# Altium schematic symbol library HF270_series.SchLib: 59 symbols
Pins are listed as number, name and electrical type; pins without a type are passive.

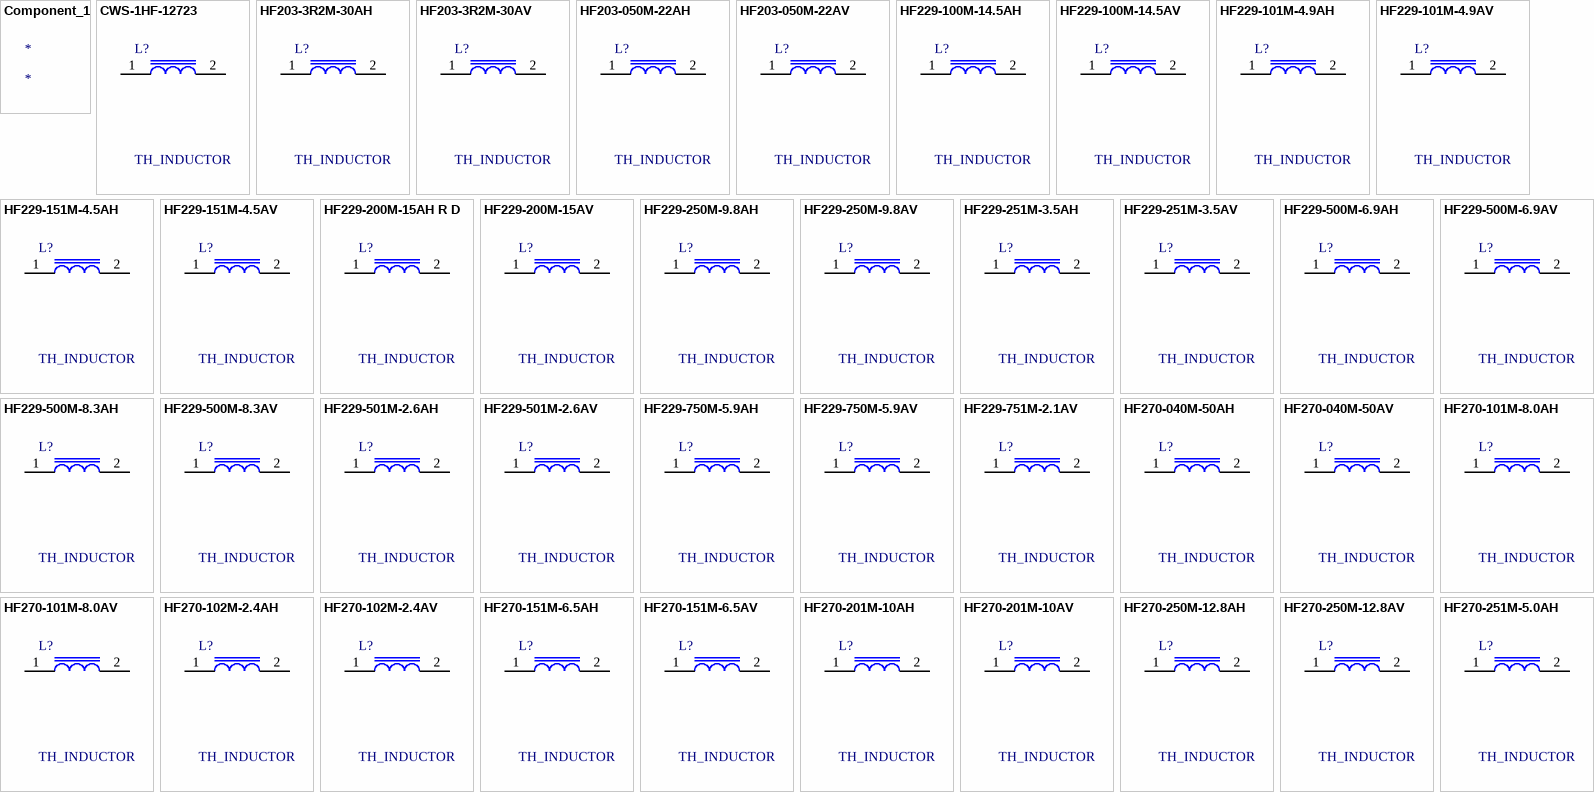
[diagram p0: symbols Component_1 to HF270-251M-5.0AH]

## Component_1
designator *

## CWS-1HF-12723
designator L?, comment TH_INDUCTOR
POWER INDUCTOR 22.0 A, 40 uH, 8 mOhms, OD 34.04 mm, HT 18.03 mm; Manufacturer #1: CWS; Sim.Analog.Prefix: L; Sim.Analog.Order: Model$; Current: 22.0 A; DCR: 8 mOhms; Inductance: 40 uH
footprint CWS-1HF-12723
pins: 1, 2

## HF203-3R2M-30AH
designator L?, comment TH_INDUCTOR
POWER INDUCTOR 30.0 A, 3.20 uH, 1 mOhms, OD 28.45 mm, HT 13.21 mm; Manufacturer #1: CWS; Sim.Analog.Prefix: L; Sim.Analog.Order: Model$; Current: 30.0 A; DCR: 1 mOhms; Inductance: 3.20 uH
footprint HF203-3R2M-30AH
pins: 1, 2

## HF203-3R2M-30AV
designator L?, comment TH_INDUCTOR
POWER INDUCTOR 30.0 A, 3.20 uH, 1 mOhms, OD 27.43 mm, HT 12.7 mm; Manufacturer #1: CWS; Sim.Analog.Prefix: L; Sim.Analog.Order: Model$; Current: 30.0 A; DCR: 1 mOhms; Inductance: 3.20 uH
footprint HF203-3R2M-30AV
pins: 1, 2

## HF203-050M-22AH
designator L?, comment TH_INDUCTOR
POWER INDUCTOR 22.0 A, 5.40 uH, 2 mOhms, OD 27 mm, HT 11.51 mm; Manufacturer #1: CWS; Sim.Analog.Prefix: L; Sim.Analog.Order: Model$; OD: 27 mm; Current: 22.0 A; DCR: 2 mOhms; Inductance: 5.40 uH
footprint HF203-050M-22AH
pins: 1, 2

## HF203-050M-22AV
designator L?, comment TH_INDUCTOR
POWER INDUCTOR 22.0 A, 5.40 uH, 2 mOhms, OD 27 mm, HT 11.51 mm; Manufacturer #1: CWS; Sim.Analog.Prefix: L; Sim.Analog.Order: Model$; OD: 27 mm; Current: 22.0 A; DCR: 2 mOhms; Inductance: 5.40 uH
footprint HF203-050M-22AV
pins: 1, 2

## HF229-100M-14.5AH
designator L?, comment TH_INDUCTOR
POWER INDUCTOR 14.5 A, 10 uH, 8 mOhms, OD 27.94 mm, HT 12.07 mm; Manufacturer #1: CWS; Sim.Analog.Prefix: L; Sim.Analog.Order: Model$; Current: 14.5 A; DCR: 8 mOhms; Inductance: 10 uH
footprint HF229-100M-14.5AH
pins: 1, 2

## HF229-100M-14.5AV
designator L?, comment TH_INDUCTOR
POWER INDUCTOR 14.5 A, 10 uH, 8 mOhms, OD 27.94 mm, HT 12.07 mm; Manufacturer #1: CWS; Sim.Analog.Prefix: L; Sim.Analog.Order: Model$; Current: 14.5 A; DCR: 8 mOhms; Inductance: 10 uH
footprint HF229-100M-14.5AV
pins: 1, 2

## HF229-101M-4.9AH
designator L?, comment TH_INDUCTOR
POWER INDUCTOR 4.9 A, 100 uH, 44 mOhms, OD 27.94 mm, HT 12.07 mm; Manufacturer #1: CWS; Sim.Analog.Prefix: L; Sim.Analog.Order: Model$; Current: 4.9 A; Inductance: 100 uH
footprint HF229-101M-4.9AH
pins: 1, 2

## HF229-101M-4.9AV
designator L?, comment TH_INDUCTOR
POWER INDUCTOR 4.9 A, 100 uH, 44 mOhms, OD 27.94 mm, HT 12.07 mm; Manufacturer #1: CWS; Sim.Analog.Prefix: L; Sim.Analog.Order: Model$; Current: 4.9 A; Inductance: 100 uH
footprint HF229-101M-4.9AV
pins: 1, 2

## HF229-151M-4.5AH
designator L?, comment TH_INDUCTOR
POWER INDUCTOR 4.5 A, 150 uH, 52 mOhms, OD 27.94 mm, HT 12.07 mm; Manufacturer #1: CWS; Sim.Analog.Prefix: L; Sim.Analog.Order: Model$; Current: 4.5 A; Inductance: 150 uH
footprint HF229-151M-4.5AH
pins: 1, 2

## HF229-151M-4.5AV
designator L?, comment TH_INDUCTOR
POWER INDUCTOR 4.5 A, 150 uH, 52 mOhms, OD 27.94 mm, HT 12.07 mm; Manufacturer #1: CWS; Sim.Analog.Prefix: L; Sim.Analog.Order: Model$; Current: 4.5 A; Inductance: 150 uH
footprint HF229-151M-4.5AV
pins: 1, 2

## HF229-200M-15AH R D
designator L?, comment TH_INDUCTOR
POWER INDUCTOR 15.0 A, 20 uH, 8 mOhms, OD 27.94 mm, HT 12.07 mm; Manufacturer #1: CWS; Sim.Analog.Prefix: L; Sim.Analog.Order: Model$; Current: 15.0 A; DCR: 8 mOhms; Inductance: 20 uH
footprint HF229-200M-15AH R D
pins: 1, 2

## HF229-200M-15AV
designator L?, comment TH_INDUCTOR
POWER INDUCTOR 15.0 A, 20 uH, 8 mOhms, OD 27.94 mm, HT 12.07 mm; Manufacturer #1: CWS; Sim.Analog.Prefix: L; Sim.Analog.Order: Model$; Current: 15.0 A; DCR: 8 mOhms; Inductance: 20 uH
footprint HF229-200M-15AV
pins: 1, 2

## HF229-250M-9.8AH
designator L?, comment TH_INDUCTOR
POWER INDUCTOR 9.8 A, 25 uH, 11 mOhms, OD 27.94 mm, HT 12.07 mm; Manufacturer #1: CWS; Sim.Analog.Prefix: L; Sim.Analog.Order: Model$; Current: 9.8 A; Inductance: 25 uH
footprint HF229-250M-9.8AH
pins: 1, 2

## HF229-250M-9.8AV
designator L?, comment TH_INDUCTOR
POWER INDUCTOR 9.8 A, 25 uH, 11 mOhms, OD 27.94 mm, HT 12.07 mm; Manufacturer #1: CWS; Sim.Analog.Prefix: L; Sim.Analog.Order: Model$; Current: 9.8 A; Inductance: 25 uH
footprint HF229-250M-9.8AV
pins: 1, 2

## HF229-251M-3.5AH
designator L?, comment TH_INDUCTOR
POWER INDUCTOR 3.5 A, 250 uH, 88 mOhms, OD 27.94 mm, HT 12.07 mm; Manufacturer #1: CWS; Sim.Analog.Prefix: L; Sim.Analog.Order: Model$; Current: 3.5 A; Inductance: 250 uH
footprint HF229-251M-3.5AH
pins: 1, 2

## HF229-251M-3.5AV
designator L?, comment TH_INDUCTOR
POWER INDUCTOR 3.5 A, 250 uH, 88 mOhms, OD 27.94 mm, HT 12.07 mm; Manufacturer #1: CWS; Sim.Analog.Prefix: L; Sim.Analog.Order: Model$; Current: 3.5 A; Inductance: 250 uH
footprint HF229-251M-3.5AV
pins: 1, 2

## HF229-500M-6.9AH
designator L?, comment TH_INDUCTOR
POWER INDUCTOR 6.9 A, 50 uH, 22 mOhms, OD 27.94 mm, HT 12.07 mm; Manufacturer #1: CWS; Sim.Analog.Prefix: L; Sim.Analog.Order: Model$; Current: 6.9 A; Inductance: 50 uH
footprint HF229-500M-6.9AH
pins: 1, 2

## HF229-500M-6.9AV
designator L?, comment TH_INDUCTOR
POWER INDUCTOR 6.9 A, 50 uH, 22 mOhms, OD 27.94 mm, HT 12.07 mm; Manufacturer #1: CWS; Sim.Analog.Prefix: L; Sim.Analog.Order: Model$; Current: 6.9 A; Inductance: 50 uH
footprint HF229-500M-6.9AV
pins: 1, 2

## HF229-500M-8.3AH
designator L?, comment TH_INDUCTOR
POWER INDUCTOR 8.3 A, 50 uH, 22 mOhms, OD 27.94 mm, HT 12.07 mm; Manufacturer #1: CWS; Sim.Analog.Prefix: L; Sim.Analog.Order: Model$; Current: 8.3 A; Inductance: 50 uH
footprint HF229-500M-8.3AH
pins: 1, 2

## HF229-500M-8.3AV
designator L?, comment TH_INDUCTOR
POWER INDUCTOR 8.3 A, 50 uH, 22 mOhms, OD 27.94 mm, HT 12.07 mm; Manufacturer #1: CWS; Sim.Analog.Prefix: L; Sim.Analog.Order: Model$; Current: 8.3 A; Inductance: 50 uH
footprint HF229-500M-8.3AV
pins: 1, 2

## HF229-501M-2.6AH
designator L?, comment TH_INDUCTOR
POWER INDUCTOR 2.6 A, 500 uH, 160 mOhms, OD 27.94 mm, HT 12.07 mm; Manufacturer #1: CWS; Sim.Analog.Prefix: L; Sim.Analog.Order: Model$; Current: 2.6 A; Inductance: 500 uH
footprint HF229-501M-2.6AH
pins: 1, 2

## HF229-501M-2.6AV
designator L?, comment TH_INDUCTOR
POWER INDUCTOR 2.6 A, 500 uH, 160 mOhms, OD 27.94 mm, HT 12.07 mm; Manufacturer #1: CWS; Sim.Analog.Prefix: L; Sim.Analog.Order: Model$; Current: 2.6 A; Inductance: 500 uH
footprint HF229-501M-2.6AV
pins: 1, 2

## HF229-750M-5.9AH
designator L?, comment TH_INDUCTOR
POWER INDUCTOR 5.9 A, 75 uH, 30 mOhms, OD 27.94 mm, HT 12.07 mm; Manufacturer #1: CWS; Sim.Analog.Prefix: L; Sim.Analog.Order: Model$; Current: 5.9 A; Inductance: 75 uH
footprint HF229-750M-5.9AH
pins: 1, 2

## HF229-750M-5.9AV
designator L?, comment TH_INDUCTOR
POWER INDUCTOR 5.9 A, 75 uH, 30 mOhms, OD 27.94 mm, HT 12.07 mm; Manufacturer #1: CWS; Sim.Analog.Prefix: L; Sim.Analog.Order: Model$; Current: 5.9 A; Inductance: 75 uH
footprint HF229-750M-5.9AV
pins: 1, 2

## HF229-751M-2.1AV
designator L?, comment TH_INDUCTOR
POWER INDUCTOR 2.1 A, 750 uH, 240 mOhms, OD 27.94 mm, HT 12.07 mm; Manufacturer #1: CWS; Sim.Analog.Prefix: L; Sim.Analog.Order: Model$; Current: 2.1 A; Inductance: 750 uH
footprint HF229-751M-2.1AV
pins: 1, 2

## HF270-040M-50AH
designator L?, comment TH_INDUCTOR
POWER INDUCTOR 50.0 A, 4 uH, 1.30 mOhms, OD 36.58 mm, HT 15.49 mm; Manufacturer #1: CWS; Sim.Analog.Prefix: L; Sim.Analog.Order: Model$; Current: 50.0 A; Inductance: 4 uH
footprint HF270-040M-50AH
pins: 1, 2

## HF270-040M-50AV
designator L?, comment TH_INDUCTOR
POWER INDUCTOR 50.0 A, 4 uH, 1.30 mOhms, OD 33.02 mm, HT 43.43 mm; Manufacturer #1: CWS; Sim.Analog.Prefix: L; Sim.Analog.Order: Model$; Current: 50.0 A; Inductance: 4 uH
footprint HF270-040M-50AV
pins: 1, 2

## HF270-101M-8.0AH
designator L?, comment TH_INDUCTOR
POWER INDUCTOR 8.0 A, 100 uH, 23 mOhms, OD 33.02 mm, HT 16.51 mm; Manufacturer #1: CWS; Sim.Analog.Prefix: L; Sim.Analog.Order: Model$; Current: 8.0 A; Inductance: 100 uH
footprint HF270-101M-8.0AH
pins: 1, 2

## HF270-101M-8.0AV
designator L?, comment TH_INDUCTOR
POWER INDUCTOR 8.0 A, 100 uH, 23 mOhms, OD 33.02 mm, HT 16.51 mm; Manufacturer #1: CWS; Sim.Analog.Prefix: L; Sim.Analog.Order: Model$; Current: 8.0 A; Inductance: 100 uH
footprint HF270-101M-8.0AV
pins: 1, 2

## HF270-102M-2.4AH
designator L?, comment TH_INDUCTOR
POWER INDUCTOR 2.4 A, 1000 uH, 235 mOhms, OD 33.02 mm, HT 16.51 mm; Manufacturer #1: CWS; Sim.Analog.Prefix: L; Sim.Analog.Order: Model$; Current: 2.4 A; Inductance: 1000 uH
footprint HF270-102M-2.4AH
pins: 1, 2

## HF270-102M-2.4AV
designator L?, comment TH_INDUCTOR
POWER INDUCTOR 2.4 A, 1000 uH, 235 mOhms, OD 33.02 mm, HT 16.51 mm; Manufacturer #1: CWS; Sim.Analog.Prefix: L; Sim.Analog.Order: Model$; Current: 2.4 A; Inductance: 1000 uH
footprint HF270-102M-2.4AV
pins: 1, 2

## HF270-151M-6.5AH
designator L?, comment TH_INDUCTOR
POWER INDUCTOR 6.5 A, 150 uH, 35 mOhms, OD 33.02 mm, HT 16.51 mm; Manufacturer #1: CWS; Sim.Analog.Prefix: L; Sim.Analog.Order: Model$; Current: 6.5 A; Inductance: 150 uH
footprint HF270-151M-6.5AH
pins: 1, 2

## HF270-151M-6.5AV
designator L?, comment TH_INDUCTOR
POWER INDUCTOR 6.5 A, 150 uH, 35 mOhms, OD 33.02 mm, HT 16.51 mm; Manufacturer #1: CWS; Sim.Analog.Prefix: L; Sim.Analog.Order: Model$; Current: 6.5 A; Inductance: 150 uH
footprint HF270-151M-6.5AV
pins: 1, 2

## HF270-201M-10AH
designator L?, comment TH_INDUCTOR
POWER INDUCTOR 10.0 A, 200 uH, 25 mOhms, OD 33.02 mm, HT 16.51 mm; Manufacturer #1: CWS; Sim.Analog.Prefix: L; Sim.Analog.Order: Model$; Current: 10.0 A; Inductance: 200 uH
footprint HF270-201M-10AH
pins: 1, 2

## HF270-201M-10AV
designator L?, comment TH_INDUCTOR
POWER INDUCTOR 10.0 A, 200 uH, 25 mOhms, OD 33.02 mm, HT 16.51 mm; Manufacturer #1: CWS; Sim.Analog.Prefix: L; Sim.Analog.Order: Model$; Current: 10.0 A; Inductance: 200 uH
footprint HF270-201M-10AV
pins: 1, 2

## HF270-250M-12.8AH
designator L?, comment TH_INDUCTOR
POWER INDUCTOR 12.8 A, 25 uH, 7 mOhms, OD 33.02 mm, HT 16.51 mm; Manufacturer #1: CWS; Sim.Analog.Prefix: L; Sim.Analog.Order: Model$; Current: 12.8 A; DCR: 7 mOhms; Inductance: 25 uH
footprint HF270-250M-12.8AH
pins: 1, 2

## HF270-250M-12.8AV
designator L?, comment TH_INDUCTOR
POWER INDUCTOR 12.8 A, 25 uH, 7 mOhms, OD 33.02 mm, HT 16.51 mm; Manufacturer #1: CWS; Sim.Analog.Prefix: L; Sim.Analog.Order: Model$; Current: 12.8 A; DCR: 7 mOhms; Inductance: 25 uH
footprint HF270-250M-12.8AV
pins: 1, 2

## HF270-251M-5.0AH
designator L?, comment TH_INDUCTOR
POWER INDUCTOR 5.0 A, 250 uH, 60 mOhms, OD 33.02 mm, HT 16.51 mm; Manufacturer #1: CWS; Sim.Analog.Prefix: L; Sim.Analog.Order: Model$; Current: 5.0 A; Inductance: 250 uH
footprint HF270-251M-5.0AH
pins: 1, 2

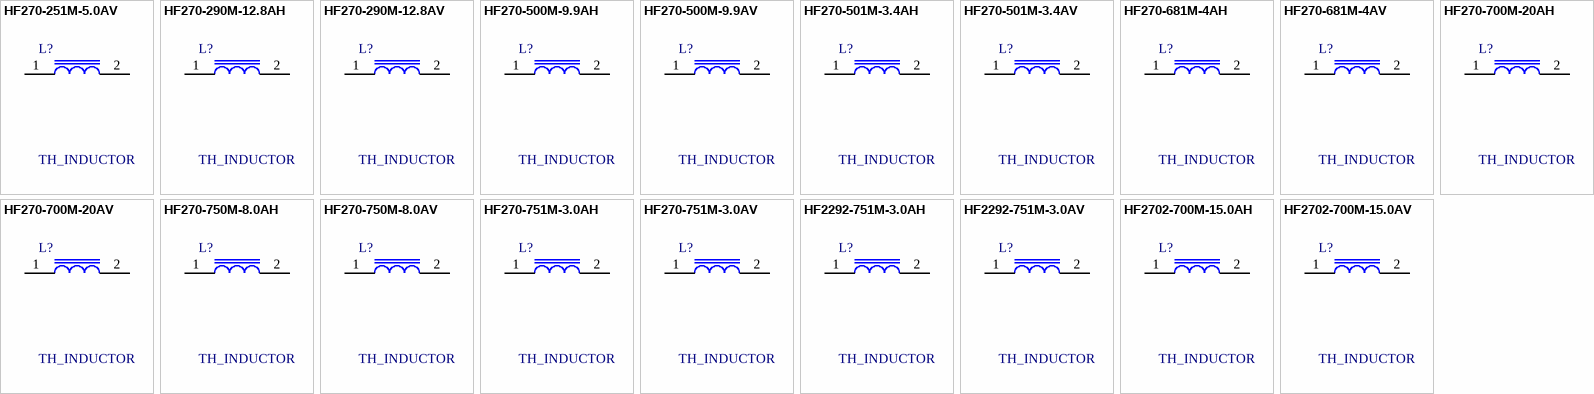
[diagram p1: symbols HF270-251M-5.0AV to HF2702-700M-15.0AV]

## HF270-251M-5.0AV
designator L?, comment TH_INDUCTOR
POWER INDUCTOR 5.0 A, 250 uH, 60 mOhms, OD 33.02 mm, HT 16.51 mm; Manufacturer #1: CWS; Sim.Analog.Prefix: L; Sim.Analog.Order: Model$; Current: 5.0 A; Inductance: 250 uH
footprint HF270-251M-5.0AV
pins: 1, 2

## HF270-290M-12.8AH
designator L?, comment TH_INDUCTOR
POWER INDUCTOR 12.8 A, 29 uH, 13 mOhms, OD 33.02 mm, HT 16.51 mm; Manufacturer #1: CWS; Sim.Analog.Prefix: L; Sim.Analog.Order: Model$; Current: 12.8 A; Inductance: 29 uH
footprint HF270-290M-12.8AH
pins: 1, 2

## HF270-290M-12.8AV
designator L?, comment TH_INDUCTOR
POWER INDUCTOR 12.8 A, 29 uH, 13 mOhms, OD 33.02 mm, HT 16.51 mm; Manufacturer #1: CWS; Sim.Analog.Prefix: L; Sim.Analog.Order: Model$; Current: 12.8 A; Inductance: 29 uH
footprint HF270-290M-12.8AV
pins: 1, 2

## HF270-500M-9.9AH
designator L?, comment TH_INDUCTOR
POWER INDUCTOR 9.9 A, 50 uH, 16 mOhms, OD 33.02 mm, HT 16.51 mm; Manufacturer #1: CWS; Sim.Analog.Prefix: L; Sim.Analog.Order: Model$; Current: 9.9 A; Inductance: 50 uH
footprint HF270-500M-9.9AH
pins: 1, 2

## HF270-500M-9.9AV
designator L?, comment TH_INDUCTOR
POWER INDUCTOR 9.9 A, 50 uH, 16 mOhms, OD 33.02 mm, HT 16.51 mm; Manufacturer #1: CWS; Sim.Analog.Prefix: L; Sim.Analog.Order: Model$; Current: 9.9 A; Inductance: 50 uH
footprint HF270-500M-9.9AV
pins: 1, 2

## HF270-501M-3.4AH
designator L?, comment TH_INDUCTOR
POWER INDUCTOR 3.4 A, 500 uH, 131 mOhms, OD 33.02 mm, HT 16.51 mm; Manufacturer #1: CWS; Sim.Analog.Prefix: L; Sim.Analog.Order: Model$; Current: 3.4 A; Inductance: 500 uH
footprint HF270-501M-3.4AH
pins: 1, 2

## HF270-501M-3.4AV
designator L?, comment TH_INDUCTOR
POWER INDUCTOR 3.4 A, 500 uH, 131 mOhms, OD 33.02 mm, HT 16.51 mm; Manufacturer #1: CWS; Sim.Analog.Prefix: L; Sim.Analog.Order: Model$; Current: 3.4 A; Inductance: 500 uH
footprint HF270-501M-3.4AV
pins: 1, 2

## HF270-681M-4AH
designator L?, comment TH_INDUCTOR
POWER INDUCTOR 4.0 A, 680 uH, 134 mOhms, OD 33.02 mm, HT 17.02 mm; Manufacturer #1: CWS; Sim.Analog.Prefix: L; Sim.Analog.Order: Model$; Current: 4.0 A; Inductance: 680 uH
footprint HF270-681M-4AH
pins: 1, 2

## HF270-681M-4AV
designator L?, comment TH_INDUCTOR
POWER INDUCTOR 4.0 A, 680 uH, 134 mOhms, OD 33.02 mm, HT 17.02 mm; Manufacturer #1: CWS; Sim.Analog.Prefix: L; Sim.Analog.Order: Model$; Current: 4.0 A; Inductance: 680 uH
footprint HF270-681M-4AV
pins: 1, 2

## HF270-700M-20AH
designator L?, comment TH_INDUCTOR
POWER INDUCTOR 20.0 A, 70 uH, 8 mOhms, OD 33.02 mm, HT 16.51 mm; Manufacturer #1: CWS; Sim.Analog.Prefix: L; Sim.Analog.Order: Model$; Current: 20.0 A; DCR: 8 mOhms; Inductance: 70 uH
footprint HF270-700M-20AH
pins: 1, 2

## HF270-700M-20AV
designator L?, comment TH_INDUCTOR
POWER INDUCTOR 20.0 A, 70 uH, 8 mOhms, OD 33.02 mm, HT 16.51 mm; Manufacturer #1: CWS; Sim.Analog.Prefix: L; Sim.Analog.Order: Model$; Current: 20.0 A; DCR: 8 mOhms; Inductance: 70 uH
footprint HF270-700M-20AV
pins: 1, 2

## HF270-750M-8.0AH
designator L?, comment TH_INDUCTOR
POWER INDUCTOR 8.0 A, 75 uH, 23 mOhms, OD 33.02 mm, HT 16.51 mm; Manufacturer #1: CWS; Sim.Analog.Prefix: L; Sim.Analog.Order: Model$; Current: 8.0 A; Inductance: 75 uH
footprint HF270-750M-8.0AH
pins: 1, 2

## HF270-750M-8.0AV
designator L?, comment TH_INDUCTOR
POWER INDUCTOR 8.0 A, 75 uH, 23 mOhms, OD 33.02 mm, HT 16.51 mm; Manufacturer #1: CWS; Sim.Analog.Prefix: L; Sim.Analog.Order: Model$; Current: 8.0 A; Inductance: 75 uH
footprint HF270-750M-8.0AV
pins: 1, 2

## HF270-751M-3.0AH
designator L?, comment TH_INDUCTOR
POWER INDUCTOR 3.0 A, 750 uH, 160 mOhms, OD 33.02 mm, HT 16.51 mm; Manufacturer #1: CWS; Sim.Analog.Prefix: L; Sim.Analog.Order: Model$; Current: 3.0 A; Inductance: 750 uH
footprint HF270-751M-3.0AH
pins: 1, 2

## HF270-751M-3.0AV
designator L?, comment TH_INDUCTOR
POWER INDUCTOR 3.0 A, 750 uH, 160 mOhms, OD 33.02 mm, HT 16.51 mm; Manufacturer #1: CWS; Sim.Analog.Prefix: L; Sim.Analog.Order: Model$; Current: 3.0 A; Inductance: 750 uH
footprint HF270-751M-3.0AV
pins: 1, 2

## HF2292-751M-3.0AH
designator L?, comment TH_INDUCTOR
POWER INDUCTOR 3.0 A, 750 uH, 180 mOhms, OD 28.7 mm, HT 20.07 mm; Manufacturer #1: CWS; Sim.Analog.Prefix: L; Sim.Analog.Order: Model$; OD: 28.7 mm; Current: 3.0 A; Inductance: 750 uH
footprint HF2292-751M-3.0AH
pins: 1, 2

## HF2292-751M-3.0AV
designator L?, comment TH_INDUCTOR
POWER INDUCTOR 3.0 A, 750 uH, 180 mOhms, OD 28.19 mm, HT 21.34 mm; Manufacturer #1: CWS; Sim.Analog.Prefix: L; Sim.Analog.Order: Model$; Current: 3.0 A; Inductance: 750 uH
footprint HF2292-751M-3.0AV
pins: 1, 2

## HF2702-700M-15.0AH
designator L?, comment TH_INDUCTOR
POWER INDUCTOR 15.0 A, 70 uH, 9 mOhms, OD 33.53 mm, HT 19.05 mm; Manufacturer #1: CWS; Sim.Analog.Prefix: L; Sim.Analog.Order: Model$; Current: 15.0 A; DCR: 9 mOhms; Inductance: 70 uH
footprint HF2702-700M-15.0AH
pins: 1, 2

## HF2702-700M-15.0AV
designator L?, comment TH_INDUCTOR
POWER INDUCTOR 15.0 A, 70 uH, 9 mOhms, OD 33.53 mm, HT 19.05 mm; Manufacturer #1: CWS; Sim.Analog.Prefix: L; Sim.Analog.Order: Model$; Current: 15.0 A; DCR: 9 mOhms; Inductance: 70 uH
footprint HF2702-700M-15.0AV
pins: 1, 2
